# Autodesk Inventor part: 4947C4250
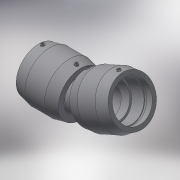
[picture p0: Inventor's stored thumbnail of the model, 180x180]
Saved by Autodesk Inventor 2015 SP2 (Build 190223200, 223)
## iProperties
Created: 2017-06
Part Number: 4947C4250
Material: Generic
Description: PLASSON ADJUSTABLE ELBOW 250
Document SubType Name: Modeling
Designer: KIM
Mass: 16853.5 g
Surface Area: 12350.1 cm^2
Volume: 16853.5 cm^3
Density: 1 g/cm^3
Appearance: Default
Author: KIM
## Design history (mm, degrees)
derived "4947C4.ipt"
feature "Solid1::4947C4.ipt"
tag "TaggingFeature1"
body "Solid1"
other parameters: "d0" = 257.6, "d2" = 312, "d3" = 123, "d4" = 61.5, "d5" = 280.8, "d8" = 168 deg, "d10" = 49.2, "d11" = 16.4, "d29" = 156, "d30" = 15, "d31" = 103.04, "d34" = 5 deg, "d41" = 4, "d42" = 14, "d43" = 0, "d48" = 225, "d49" = 24 deg, "d50" = 644, "d51" = 78 deg, "d52" = 90 deg, "d55" = 67.3, "d57" = 168 deg, "d58" = 13.46, "d60" = 78.03467, "d62" = 3, "d63" = 0, "L_" = 644, "L_1" = 123, "D_" = 312, "A_" = 156, "d_2" = 12, "L_0" = 148, "d54" = 134.6, "d59" = 260.11555
